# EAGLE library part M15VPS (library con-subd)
SUB-D
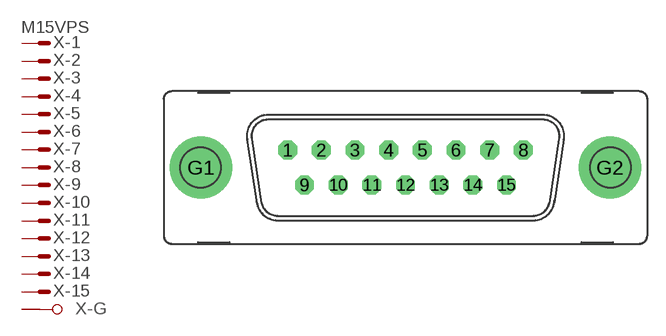
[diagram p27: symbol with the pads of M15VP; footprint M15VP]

Designator prefix X; gates -2=M -3=M -4=M -5=M -6=M -7=M -8=M -9=M -10=M -11=M -12=M -13=M -14=M -15=M -G=GND -1=MV

## M15VPS (OC_FARNELL: unknown; OC_NEWARK: unknown)  [M15VP]
1  -1:M  pas
2  -2:M  pas
3  -3:M  pas
4  -4:M  pas
5  -5:M  pas
6  -6:M  pas
7  -7:M  pas
8  -8:M  pas
9  -9:M  pas
10  -10:M  pas
11  -11:M  pas
12  -12:M  pas
13  -13:M  pas
14  -14:M  pas
15  -15:M  pas
G1  -G:G1  pas
G2  -G:G2  pas

## Footprint M15VP (pad centres in mm)
SUB-D
drill 1.016 octagon: 1 -9.601,1.422; 2 -6.858,1.422; 3 -4.115,1.422; 4 -1.372,1.422; 5 1.372,1.422; 6 4.115,1.422; 7 6.858,1.422; 8 9.601,1.422; 9 -8.23,-1.422; 10 -5.486,-1.422; 11 -2.743,-1.422; 12 0,-1.422; 13 2.743,-1.422; 14 5.486,-1.422; 15 8.23,-1.422
drill 3.302 pad 5.08 round: G1 -16.662,0; G2 16.662,0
